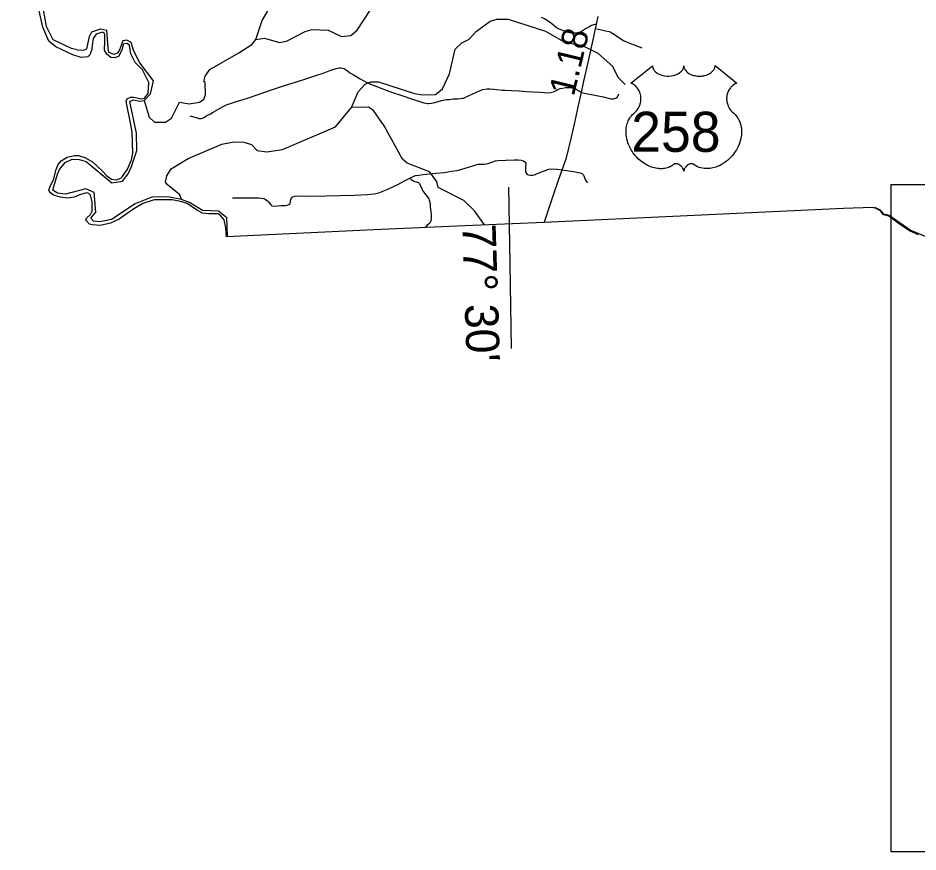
# Model space of a CAD drawing. Extents: x 2290615 to 2522933, y 819489 to 1012715.
# Drawn here: x 2434201 to 2451720, y 823594 to 839817 of the extents above; entities that cross this region are included whole.
import ezdxf

# ---------------------------------------------------------------- set-up
doc = ezdxf.new("R2010")
doc.units = 0
for name, color, linetype in [('Exist Boundary Political CountyLine', 7, 'Continuous'), ('Exist Hydrographic Misc Water Feature', 7, 'Continuous'), ('Exist Road Non-System Type 51', 7, 'Continuous'), ('Exist Road Primary US Attributed', 7, 'Continuous'), ('Exist Road Primary US Mileage Hundredths English Label', 7, 'Continuous'), ('Exist Road Primary US Shield CELL', 7, 'Continuous'), ('Exist Road Primary US Shield Number Label', 7, 'Continuous'), ('Map Preparation Inset Cut Line', 7, 'Continuous'), ('Map Preparation Longitude Latitude Label', 7, 'Continuous'), ('Map Preparation Longitude Latitude Lines', 7, 'Continuous')]:
    doc.layers.add(name, color=color, linetype=linetype)

msp = doc.modelspace()

# ---------------------------------------------------------------- linework, layer by layer
at = {"layer": 'Exist Boundary Political CountyLine'}
for points in [[(2435800, 835779), (2435644, 835795), (2435593, 835810), (2435524, 835883), (2435536, 835921), (2435612, 835992), (2435644, 836057), (2435647, 836241), (2435613, 836374), (2435581, 836402), (2435540, 836417), (2435415, 836387), (2435296, 836333), (2435168, 836312), (2435026, 836330), (2434893, 836370), (2434833, 836415), (2434802, 836470), (2434837, 836559), (2434891, 836670), (2434942, 836872), (2434981, 836965), (2435040, 837036), (2435157, 837107), (2435304, 837140), (2435382, 837140), (2435505, 837106), (2435652, 837020), (2435838, 836843), (2435932, 836747), (2436019, 836680), (2436113, 836669), (2436200, 836700), (2436234, 836737), (2436332, 836875), (2436409, 837058), (2436437, 837190), (2436421, 837596), (2436382, 837809), (2436319, 838126), (2436304, 838206), (2436332, 838252), (2436393, 838279), (2436457, 838276), (2436604, 838246), (2436664, 838259), (2436732, 838350), (2436747, 838564), (2436622, 838812), (2436482, 838954), (2436399, 839121), (2436369, 839287), (2436318, 839320), (2436250, 839311), (2436232, 839211), (2436162, 839074), (2436084, 839043), (2436006, 839052), (2435931, 839112), (2435888, 839192), (2435890, 839364), (2435894, 839492), (2435885, 839520), (2435843, 839543), (2435720, 839503), (2435665, 839420), (2435647, 839288), (2435640, 839204), (2435600, 839100), (2435558, 839061), (2435428, 839051), (2435266, 839099), (2434941, 839258), (2434802, 839368), (2434686, 839638), (2434611, 839959)], [(2438263, 835559), (2438250, 835736), (2438215, 835889), (2438150, 835972), (2438097, 836007), (2438032, 836007), (2437915, 836007), (2437791, 836019), (2437697, 836072), (2437496, 836207), (2437367, 836249), (2437202, 836278), (2436854, 836278), (2436630, 836207), (2436435, 836095), (2436170, 835901), (2436001, 835828), (2435800, 835779)], [(2450843, 836129), (2450267, 836112), (2447226, 835967), (2444444, 835840), (2442593, 835761), (2441128, 835694), (2438263, 835559)], [(2451730, 835597), (2451565, 835668), (2451359, 835804), (2451153, 835963), (2451047, 835986), (2450996, 836057), (2450908, 836114), (2450843, 836129)]]:
    msp.add_lwpolyline(points, dxfattribs=at)
at = {"layer": 'Exist Hydrographic Misc Water Feature'}
for points in [[(2438833, 839401), (2438952, 839771), (2439058, 839946), (2439146, 840205), (2439147, 840672), (2439280, 841291), (2439304, 841348), (2439428, 841441), (2439784, 841564), (2440047, 841844), (2440333, 842263), (2440432, 842306), (2440682, 842326), (2440772, 842402), (2440985, 842680), (2441083, 842766), (2441713, 843002), (2442151, 843256), (2442576, 843865), (2442824, 843999), (2443039, 844077), (2443231, 844049), (2443446, 843818)], [(2438833, 839401), (2438999, 839428), (2439292, 839341), (2439425, 839367), (2439789, 839555), (2439930, 839591), (2440238, 839580), (2440498, 839460), (2440681, 839477), (2440805, 839580), (2441049, 839958), (2441841, 841070), (2441914, 841238), (2441936, 841462), (2441916, 841661), (2441963, 841847), (2441931, 842361), (2441879, 842510), (2441828, 842577), (2441819, 842635), (2441734, 842701)], [(2435355, 839197), (2435246, 839221), (2434888, 839391), (2434757, 839655), (2434672, 840135), (2434757, 840357), (2434733, 840533), (2434541, 840624), (2434268, 840503), (2434201, 840293)], [(2440693, 838079), (2440822, 838380), (2440961, 838533), (2441069, 838574), (2441219, 838576), (2441922, 838346), (2442073, 838322), (2442331, 838326), (2442463, 838437), (2442600, 838731), (2442710, 839208), (2442841, 839335), (2442982, 839403), (2443129, 839564), (2443393, 839758), (2443507, 839786)], [(2446017, 838523), (2445882, 838662), (2445779, 838877), (2445491, 839125), (2445248, 839253), (2444829, 839354), (2444476, 839556), (2443748, 839789), (2443507, 839786)], [(2435355, 839197), (2435477, 839191), (2435540, 839218), (2435592, 839458), (2435637, 839549), (2435810, 839607), (2435926, 839583), (2435953, 839233), (2435965, 839151)], [(2436660, 838214), (2436783, 838341), (2436841, 838594), (2436571, 838948), (2436453, 839170), (2436402, 839339), (2436321, 839384), (2436239, 839371), (2436186, 839211), (2436135, 839131), (2436069, 839106), (2435965, 839151)], [(2436660, 838214), (2436755, 837889), (2436856, 837788), (2437073, 837793), (2437188, 837870), (2437342, 838178), (2437534, 838150), (2437734, 838178), (2437816, 838237), (2437848, 838321), (2437845, 838560), (2437820, 838585), (2437843, 838688), (2437933, 838813), (2438503, 839138), (2438751, 839300), (2438833, 839401)], [(2437383, 836284), (2437118, 836339), (2436807, 836330), (2436483, 836204), (2436019, 835895), (2435792, 835849), (2435668, 835868), (2435617, 835922), (2435714, 836040), (2435684, 836423), (2435525, 836495), (2435125, 836389), (2434970, 836410), (2434881, 836465), (2434902, 836537), (2434971, 836778), (2435007, 836869), (2435117, 837008), (2435256, 837071), (2435392, 837068), (2435526, 837028), (2436029, 836612), (2436235, 836642), (2436346, 836789), (2436411, 836926), (2436515, 837237), (2436506, 837578), (2436389, 838127), (2436380, 838194), (2436447, 838225), (2436576, 838201), (2436660, 838214)], [(2437383, 836284), (2437352, 836380), (2437107, 836577), (2437073, 836624), (2437096, 836744), (2437186, 836885), (2437516, 837083), (2438171, 837365), (2438403, 837411), (2438595, 837399), (2438745, 837359), (2438856, 837242), (2439047, 837214), (2439347, 837259), (2440382, 837699), (2440693, 838079)], [(2443280, 835791), (2443089, 836063), (2442877, 836267), (2442382, 836520), (2442355, 836637), (2442211, 836824), (2441775, 836994), (2441683, 837069), (2441331, 837721), (2441119, 838017), (2441026, 838083), (2440693, 838079)], [(2438281, 835575), (2438264, 835932), (2438101, 836062), (2437790, 836075), (2437539, 836228), (2437383, 836284)], [(2451881, 835560), (2451566, 835691), (2451161, 835974), (2451055, 836000), (2450990, 836079), (2450879, 836131)]]:
    msp.add_lwpolyline(points, dxfattribs=at)
at = {"layer": 'Exist Road Non-System Type 51'}
msp.add_line((2444450, 835854), (2444525, 835844), dxfattribs=at)
msp.add_line((2444450, 835854), (2444525, 835844), dxfattribs=at)
for points in [[(2445462, 839690), (2445430, 839689), (2445401, 839684), (2445362, 839670), (2445311, 839642), (2445248, 839609), (2445199, 839575), (2445148, 839544), (2445092, 839530), (2445052, 839525), (2445000, 839526), (2444944, 839531), (2444885, 839549), (2444843, 839562), (2444738, 839599), (2444677, 839634), (2444634, 839669), (2444565, 839723), (2444518, 839759), (2444449, 839804), (2444392, 839824)], [(2445443, 839615), (2445561, 839587), (2445639, 839568), (2445707, 839553), (2445739, 839542), (2445782, 839515), (2445870, 839457), (2445917, 839422), (2445923, 839418), (2445988, 839378), (2446071, 839338), (2446140, 839312), (2446192, 839293), (2446343, 839240)], [(2445443, 839615), (2445561, 839587), (2445639, 839568), (2445707, 839553), (2445739, 839542), (2445782, 839515), (2445870, 839457), (2445917, 839422), (2445923, 839418), (2445988, 839378), (2446071, 839338), (2446140, 839312), (2446192, 839293), (2446343, 839240)], [(2437547, 837911), (2437670, 837879), (2437723, 837864), (2437764, 837862), (2437793, 837866), (2437829, 837891), (2437876, 837918), (2437949, 837955), (2438001, 837983), (2438092, 838035), (2438195, 838095), (2438274, 838133), (2438336, 838157), (2438445, 838191), (2438566, 838225), (2438705, 838273), (2438854, 838320), (2439003, 838374), (2439133, 838418), (2439330, 838482), (2439475, 838527), (2439600, 838568), (2439783, 838627), (2439998, 838698), (2440162, 838752), (2440293, 838800), (2440394, 838834), (2440462, 838849), (2440492, 838849), (2440520, 838843), (2440546, 838833), (2440569, 838821), (2440590, 838812), (2440614, 838791), (2440663, 838752), (2440747, 838705), (2440809, 838668), (2440863, 838637), (2441004, 838559), (2441093, 838517), (2441153, 838495), (2441232, 838468), (2441370, 838415), (2441494, 838370), (2441654, 838315), (2441897, 838235), (2442045, 838188), (2442100, 838169), (2442138, 838161), (2442164, 838156), (2442186, 838154), (2442248, 838161), (2442316, 838174), (2442445, 838214), (2442543, 838232), (2442607, 838235), (2442665, 838243), (2442724, 838245), (2442765, 838245), (2442823, 838251), (2442850, 838255), (2442877, 838261), (2442922, 838281), (2442998, 838318), (2443111, 838369), (2443196, 838408), (2443250, 838427), (2443336, 838441), (2443388, 838440), (2443466, 838435), (2443523, 838429), (2443632, 838416), (2443679, 838414), (2443810, 838408), (2443959, 838399), (2444101, 838389), (2444223, 838380), (2444369, 838373), (2444513, 838364), (2444569, 838369), (2444623, 838384), (2444675, 838404), (2444718, 838428), (2444756, 838444), (2444802, 838455), (2444860, 838464), (2444937, 838464), (2444981, 838462), (2445012, 838458), (2445036, 838450), (2445052, 838443), (2445079, 838420), (2445128, 838393), (2445167, 838365), (2445291, 838344), (2445394, 838323), (2445591, 838281), (2445742, 838245), (2445802, 838246), (2445837, 838258)], [(2445837, 838258), (2445871, 838282), (2445898, 838339)], [(2441829, 836699), (2441865, 836722), (2441895, 836736), (2441936, 836751), (2442002, 836760), (2442089, 836775), (2442340, 836798), (2442502, 836813), (2442637, 836837), (2442748, 836854), (2442906, 836893), (2443071, 836945), (2443155, 836975), (2443272, 836977), (2443356, 836985), (2443495, 837036), (2443545, 837043), (2443698, 837055), (2443868, 837057), (2443938, 837058), (2443994, 837053), (2444040, 837036), (2444071, 837013), (2444086, 836996), (2444080, 836893), (2444080, 836825), (2444096, 836790), (2444109, 836774), (2444134, 836768), (2444177, 836763), (2444218, 836763), (2444253, 836768), (2444280, 836779), (2444357, 836810), (2444427, 836839), (2444484, 836858), (2444510, 836868), (2444532, 836874), (2444576, 836886), (2444697, 836879), (2444794, 836864), (2445014, 836832), (2445102, 836812), (2445143, 836803), (2445177, 836790), (2445189, 836783), (2445202, 836773), (2445216, 836749), (2445225, 836717), (2445240, 836676), (2445259, 836642), (2445287, 836608)], [(2438377, 836317), (2438581, 836316), (2438789, 836317), (2438889, 836318), (2438941, 836315), (2438985, 836306), (2439012, 836292), (2439058, 836263), (2439078, 836241), (2439121, 836186), (2439145, 836162), (2439189, 836154), (2439248, 836161), (2439324, 836170), (2439406, 836172), (2439439, 836176), (2439473, 836189), (2439497, 836206), (2439510, 836291), (2439534, 836322), (2439554, 836339), (2439582, 836352), (2439666, 836356), (2439917, 836353), (2440744, 836373), (2441004, 836385), (2441136, 836395), (2441227, 836414), (2441390, 836479), (2441525, 836546), (2441594, 836581), (2441724, 836653), (2441829, 836699)], [(2441829, 836699), (2441855, 836676), (2441918, 836640), (2441952, 836631), (2441970, 836627), (2441980, 836625), (2441998, 836616), (2442017, 836598), (2442035, 836552), (2442042, 836534), (2442060, 836499), (2442077, 836461), (2442111, 836411), (2442140, 836380), (2442164, 836344), (2442197, 836298), (2442206, 836271), (2442215, 836242), (2442219, 836221), (2442223, 836188), (2442223, 836169), (2442225, 836136), (2442236, 836051), (2442241, 835990), (2442244, 835925), (2442239, 835865), (2442219, 835827), (2442183, 835799), (2442156, 835778), (2442136, 835740)]]:
    msp.add_lwpolyline(points, dxfattribs=at)
at = {"layer": 'Exist Road Primary US Attributed'}
msp.add_lwpolyline([(2444444, 835840), (2444450, 835854), (2444625, 836380), (2444724, 836662), (2444794, 836864), (2444875, 837096), (2444974, 837501), (2445033, 837755), (2445113, 838113), (2445167, 838365), (2445215, 838588), (2445297, 838953), (2445407, 839449), (2445443, 839615), (2445462, 839690), (2445495, 839845)], dxfattribs=at)
at = {"layer": 'Exist Road Primary US Shield CELL'}
msp.add_lwpolyline([(2446552, 838889), (2446554, 838872), (2446558, 838851), (2446561, 838840), (2446571, 838820), (2446587, 838795), (2446609, 838771), (2446635, 838750), (2446652, 838739), (2446681, 838724), (2446714, 838710), (2446750, 838700), (2446788, 838692), (2446829, 838687), (2446869, 838687), (2446913, 838690), (2446961, 838699), (2446983, 838705), (2447008, 838714), (2447031, 838723), (2447057, 838737), (2447077, 838750), (2447093, 838761), (2447116, 838783), (2447133, 838805), (2447141, 838818), (2447148, 838830), (2447156, 838855), (2447159, 838867), (2447161, 838890), (2447162, 838871), (2447164, 838858), (2447168, 838846), (2447173, 838833), (2447182, 838815), (2447192, 838800), (2447211, 838778), (2447222, 838767), (2447233, 838758), (2447262, 838738), (2447296, 838721), (2447312, 838714), (2447329, 838708), (2447351, 838701), (2447373, 838696), (2447395, 838692), (2447418, 838689), (2447441, 838687), (2447460, 838687), (2447483, 838687), (2447504, 838688), (2447526, 838691), (2447550, 838695), (2447570, 838699), (2447595, 838706), (2447618, 838714), (2447639, 838723), (2447665, 838737), (2447686, 838750), (2447702, 838763), (2447721, 838780), (2447738, 838800), (2447748, 838815), (2447756, 838830), (2447763, 838846), (2447767, 838863), (2447769, 838878), (2447769, 838891), (2448194, 838552), (2448184, 838548), (2448161, 838537), (2448143, 838526), (2448114, 838506), (2448101, 838494), (2448088, 838482), (2448077, 838470), (2448067, 838458), (2448054, 838441), (2448043, 838424), (2448033, 838405), (2448025, 838389), (2448012, 838355), (2448005, 838333), (2448001, 838315), (2447996, 838277), (2447995, 838259), (2447995, 838241), (2447996, 838222), (2447998, 838204), (2448001, 838185), (2448004, 838168), (2448009, 838148), (2448017, 838125), (2448026, 838102), (2448046, 838065), (2448071, 838027), (2448088, 838006), (2448106, 837988), (2448132, 837966), (2448146, 837953), (2448163, 837937), (2448189, 837906), (2448200, 837891), (2448211, 837875), (2448221, 837858), (2448231, 837840), (2448239, 837824), (2448254, 837788), (2448265, 837752), (2448270, 837734), (2448278, 837692), (2448281, 837672), (2448284, 837631), (2448284, 837582), (2448281, 837535), (2448272, 837480), (2448265, 837448), (2448253, 837410), (2448243, 837377), (2448223, 837328), (2448206, 837293), (2448184, 837252), (2448168, 837227), (2448150, 837201), (2448128, 837170), (2448102, 837137), (2448071, 837103), (2448045, 837078), (2448012, 837048), (2447992, 837031), (2447963, 837010), (2447924, 836984), (2447886, 836961), (2447853, 836944), (2447824, 836932), (2447786, 836918), (2447723, 836900), (2447700, 836895), (2447673, 836891), (2447648, 836889), (2447623, 836887), (2447590, 836887), (2447557, 836890), (2447526, 836894), (2447494, 836901), (2447460, 836911), (2447429, 836923), (2447398, 836939), (2447345, 836972), (2447330, 836980), (2447322, 836982), (2447301, 836983), (2447282, 836979), (2447263, 836971), (2447251, 836965), (2447235, 836955), (2447223, 836945), (2447208, 836931), (2447198, 836920), (2447191, 836911), (2447176, 836887), (2447171, 836876), (2447165, 836862), (2447160, 836841), (2447154, 836868), (2447146, 836885), (2447137, 836900), (2447127, 836913), (2447113, 836931), (2447099, 836943), (2447083, 836956), (2447066, 836967), (2447052, 836974), (2447040, 836979), (2447025, 836982), (2447012, 836983), (2447002, 836983), (2446988, 836980), (2446968, 836966), (2446950, 836953), (2446930, 836941), (2446907, 836929), (2446889, 836921), (2446869, 836912), (2446845, 836904), (2446819, 836898), (2446792, 836892), (2446768, 836889), (2446743, 836886), (2446720, 836886), (2446696, 836886), (2446674, 836888), (2446648, 836890), (2446616, 836895), (2446589, 836901), (2446561, 836908), (2446532, 836917), (2446501, 836929), (2446463, 836946), (2446436, 836960), (2446393, 836984), (2446344, 837018), (2446306, 837049), (2446278, 837074), (2446238, 837115), (2446214, 837142), (2446177, 837190), (2446153, 837225), (2446138, 837251), (2446115, 837292), (2446103, 837318), (2446087, 837355), (2446074, 837390), (2446063, 837422), (2446058, 837443), (2446050, 837480), (2446045, 837506), (2446040, 837541), (2446037, 837578), (2446037, 837613), (2446038, 837641), (2446041, 837675), (2446047, 837710), (2446054, 837741), (2446060, 837763), (2446069, 837789), (2446081, 837819), (2446095, 837847), (2446108, 837870), (2446125, 837895), (2446142, 837917), (2446163, 837940), (2446186, 837962), (2446207, 837979), (2446231, 838003), (2446244, 838017), (2446259, 838038), (2446272, 838056), (2446282, 838073), (2446294, 838098), (2446302, 838117), (2446312, 838145), (2446317, 838165), (2446322, 838191), (2446325, 838216), (2446326, 838246), (2446326, 838271), (2446322, 838301), (2446317, 838329), (2446310, 838353), (2446300, 838381), (2446290, 838402), (2446274, 838430), (2446256, 838456), (2446237, 838477), (2446218, 838496), (2446200, 838510), (2446183, 838522), (2446161, 838535), (2446140, 838546), (2446127, 838551)], close=True, dxfattribs=at)
at = {"layer": 'Map Preparation Inset Cut Line'}
msp.add_lwpolyline([(2451196, 836576), (2482666, 836576), (2482666, 823594), (2451196, 823594)], close=True, dxfattribs=at)
at = {"layer": 'Map Preparation Longitude Latitude Lines'}
msp.add_lwpolyline([(2443805, 833389), (2443780, 835032), (2443757, 836528)], dxfattribs=at)

# ---------------------------------------------------------------- texts
at = {"layer": 'Exist Road Primary US Mileage Hundredths English Label'}
msp.add_text('1.18', height=500, rotation=76.5125, dxfattribs=at).set_placement((2445019, 838278))
at = {"layer": 'Exist Road Primary US Shield Number Label'}
msp.add_text('258', height=780, dxfattribs=at).set_placement((2446137, 837214))
at = {"layer": 'Map Preparation Longitude Latitude Label'}
msp.add_text("77° 30'", height=650, rotation=271.8174, dxfattribs=at).set_placement((2442848, 835803))

doc.saveas('drawing.dxf')
